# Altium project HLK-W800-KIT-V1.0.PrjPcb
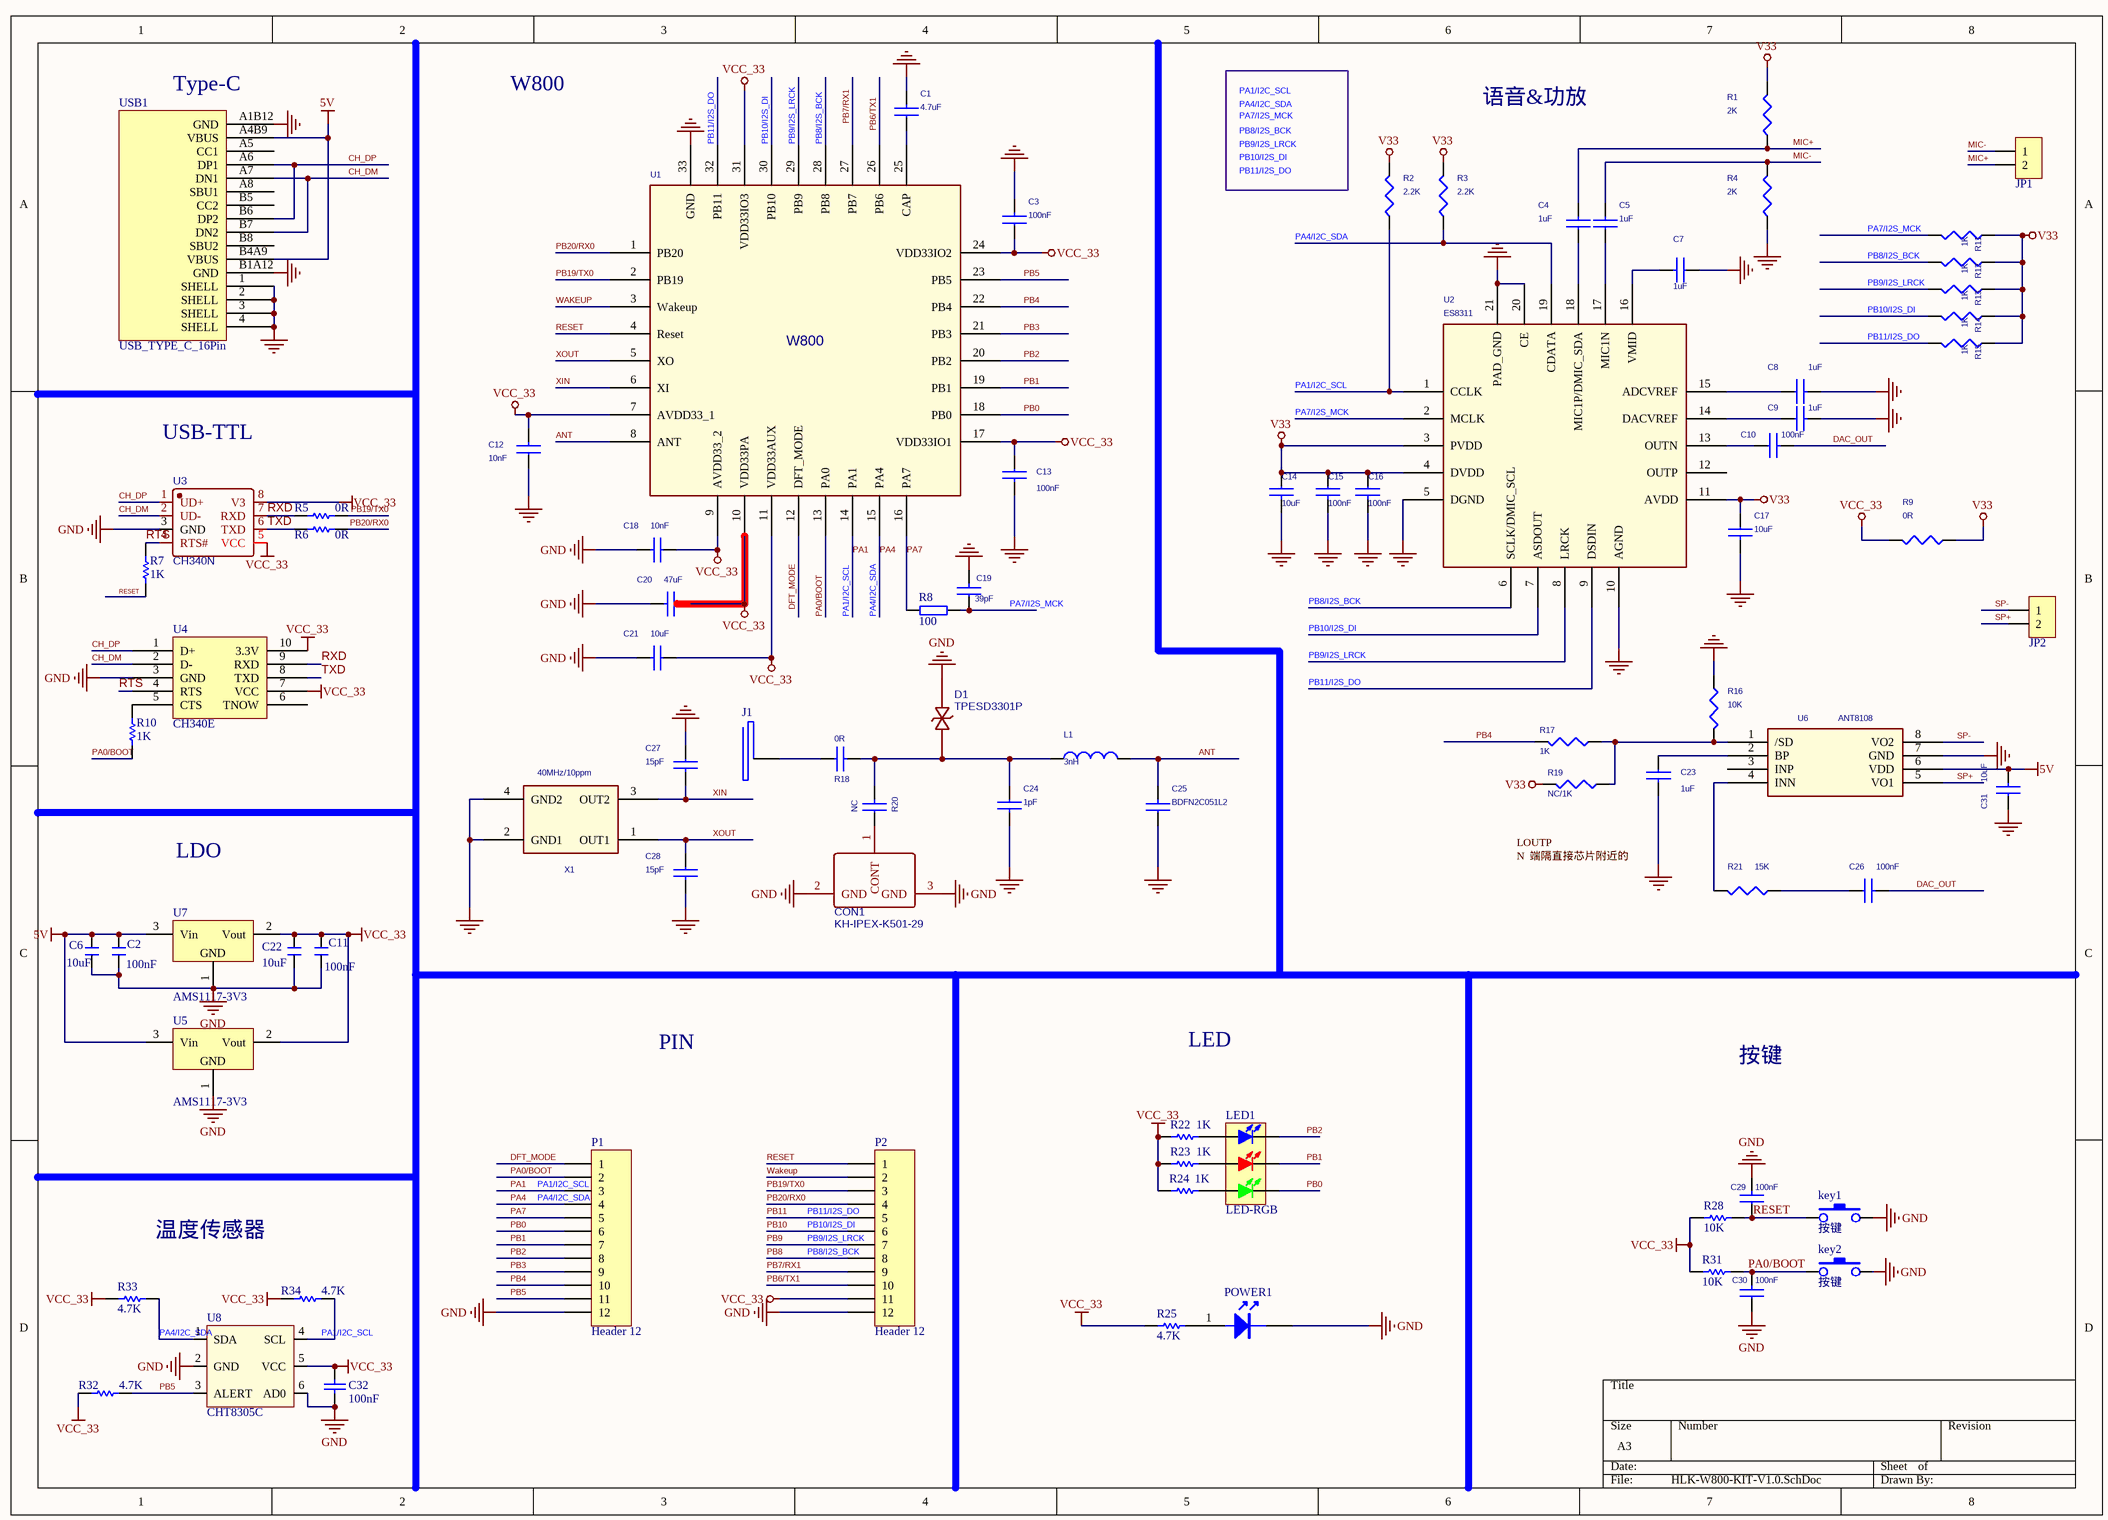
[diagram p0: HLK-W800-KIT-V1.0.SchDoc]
1 sheet, 84 parts. Net scope: global (net labels, ports and power ports of the same name join across sheets).
Board file: HLK-W800-KIT-V1.0.PcbDoc

## Sheet HLK-W800-KIT-V1.0.SchDoc
size A3

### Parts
C1  4.7uF  [C 0402_L]
C2  100nF  [C 0603_L]
C3  100nF  [C 0402_L]
C4  1uF  [C 0402_L]
C5  1uF  [C 0402_L]
C6  10uF  [C 0603_L]
C7  1uF  [C 0402_L]
C8  1uF  [C 0402_L]
C9  1uF  [C 0402_L]
C10  100nF  [C 0402_L]
C11  100nF  [C 0603_L]
C12  10nF  [C 0402_L]
C13  100nF  [C 0402_L]
C14  10uF  [C 0402_L]
C15  100nF  [C 0402_L]
C16  100nF  [C 0402_L]
C17  10uF  [C 0402_L]
C18  10nF  [C 0402_L]
C19  39pF  [C 0402_L]
C20  47uF  [C 0805_L]
C21  10uF  [C 0603_L]
C22  10uF  [C 0603_L]
C23  1uF  [C 0402_L]
C24  1pF  [C 0402_L]
C25  BDFN2C051L2  [C 0402_L]
C26  100nF  [C 0402_L]
C27  15pF  [C 0402_L]
C28  15pF  [C 0402_L]
C29  100nF  [0603]
C30  100nF  [0603]
C31  10uF  [C 0402_L]
C32  100nF  [C 0603_L]
CON1  KH-IPEX-K501-29  [SMA/UFLR/NI]
D1  TPESD3301P  [C 0402_L]
J1  (no value)  [TX1]
JP1  HDR-1X2  [MX 1.25-LS-2P]  (value not drawn)
JP2  HDR-1X2  [PH2.0-LS-2P]  (value not drawn)
key1  按键  [正按小龟]
key2  按键  [正按小龟]
L1  3nH  [0402A]
LED1  LED-RGB  [LED 5050]
P1  Header 12  [HDR1X12]
P2  Header 12  [HDR1X12]
POWER1  (no value)  [LED0603]
R1  2K  [R 0402_L]
R2  2.2K  [R 0402_L]
R3  2.2K  [R 0402_L]
R4  2K  [R 0402_L]
R5  0R  [R 0603_L]
R6  0R  [R 0603_L]
R7  1K  [R 0603_L]
R8  100  [R 0402_L]
R9  0R  [R 0805_L]
R10  1K  [R 0603_L]
R11  1K  [R 0402_L]
R12  1K  [R 0402_L]
R13  1K  [R 0402_L]
R14  1K  [R 0402_L]
R15  1K  [R 0402_L]
R16  10K  [R 0402_L]
R17  1K  [R 0402_L]
R18  0R  [C 0402_L]
R19  NC/1K  [R 0402_L]
R20  NC  [C 0402_L]
R21  15K  [R 0402_L]
R22  1K  [R 0603_L]
R23  1K  [R 0603_L]
R24  1K  [R 0603_L]
R25  4.7K  [R 0603_L]
R28  10K  [0603]
R31  10K  [0603]
R32  4.7K  [R 0603_L]
R33  4.7K  [R 0603_L]
R34  4.7K  [R 0603_L]
U1  W800  [QFN32_4X4]
U2  ES8311  [ES8311]
U3  CH340N  [SOP8_L]
U4  CH340E  [MSOP10_L]
U5  AMS1117-3V3  [SOT89_L]
U6  ANT8108  [SOP8_L]
U7  AMS1117-3V3  [SOT223_L]
U8  CHT8305C  [DFN6 3X3]
USB1  USB_TYPE_C_16Pin  [USB-C-16PIN-1]
X1  40MHz/10ppm  [SMD-3225]

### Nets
5V: C2.2 C6.2 C31.2 U5.3(Vin) U6.6(VDD) U7.3(Vin) USB1.A4B9(VBUS) USB1.B4A9(VBUS)
GND: C1.2 C2.1 C3.2 C6.1 C7.1 C8.2 C9.2 C11.1 C12.1 C13.2 C14.2 C15.2 C16.2 C17.2 C18.2 C19.2 C20.2 C21.2 C22.1 C23.2 C24.2 C25.1 C27.1 C28.2 C29.2 C30.1 C31.1 C32.2 CON1.2(GND) CON1.3(GND) D1.2 key1.2 key2.2 P1.12 P2.12 POWER1.2(K) R4.2 R16.1 U1.33(GND) U2.5(DGND) U2.10(AGND) U2.20(CE) U2.21(PAD_GND) U3.3(GND) U4.3(GND) U5.1(GND) U6.7(GND) U7.1(GND) U8.2(GND) U8.6(AD0) USB1.1(SHELL) USB1.2(SHELL) USB1.3(SHELL) USB1.4(SHELL) USB1.A1B12(GND) USB1.B1A12(GND) X1.2(GND1) X1.4(GND2)
V33: C14.1 C15.1 C16.1 C17.1 R1.1 R2.2 R3.2 R9.1 R11.1 R12.1 R13.1 R14.1 R15.1 R19.2 U2.3(PVDD) U2.4(DVDD) U2.11(AVDD)
VCC_33: C3.1 C11.2 C12.2 C13.1 C18.1 C20.1 C21.1 C22.2 C32.1 P2.11 R9.2 R22.1 R23.1 R24.1 R25.1 R28.2 R31.2 R32.1 R33.2 R34.1 U1.7(AVDD33_1) U1.9(AVDD33_2) U1.10(VDD33PA) U1.11(VDD33AUX) U1.17(VDD33IO1) U1.24(VDD33IO2) U1.31(VDD33IO3) U3.5(VCC) U3.8(V3) U4.7(VCC) U4.10(3.3V) U5.2(Vout) U7.2(Vout) U8.5(VCC)
ANT: C25.2 L1.1 U1.8(ANT)
CH_DM: U3.2(UD-) U4.2(D-) USB1.A7(DN1) USB1.B7(DN2)
CH_DP: U3.1(UD+) U4.1(D+) USB1.A6(DP1) USB1.B6(DP2)
DAC_OUT: C10.2 C26.2
DFT_MODE: P1.1 U1.12(DFT_MODE)
MIC+: C4.2 JP1.2 R1.2
MIC-: C5.2 JP1.1 R4.1
PA0/BOOT: C30.2 key2.1 P1.2 R10.1 R31.1 U1.13(PA0)
PA1: P1.3 R2.1 R34.2 U1.14(PA1) U2.1(CCLK) U8.4(SCL)  [also labelled PA1/I2C_SCL]
PA4: P1.4 R3.1 R33.1 U1.15(PA4) U2.19(CDATA) U8.1(SDA)  [also labelled PA4/I2C_SDA]
PA7: P1.5 R8.1 U1.16(PA7)
PA7/I2S_MCK: C19.1 R8.2 R11.2 U2.2(MCLK)
PB0: LED1.4(GREEN_K) P1.6 U1.18(PB0)
PB1: LED1.5(RED_K) P1.7 U1.19(PB1)
PB2: LED1.6(BULE_K) P1.8 U1.20(PB2)
PB3: P1.9 U1.21(PB3)
PB4: P1.10 R17.2 U1.22(PB4)
PB5: P1.11 R32.2 U1.23(PB5) U8.3(ALERT)
PB6/TX1: P2.10 U1.26(PB6)
PB7/RX1: P2.9 U1.27(PB7)
PB8: P2.8 R12.2 U1.28(PB8) U2.6(SCLK/DMIC_SCL)  [also labelled PB8/I2S_BCK]
PB9: P2.7 R13.2 U1.29(PB9) U2.8(LRCK)  [also labelled PB9/I2S_LRCK]
PB10: P2.6 R14.2 U1.30(PB10) U2.7(ASDOUT)  [also labelled PB10/I2S_DI]
PB11: P2.5 R15.2 U1.32(PB11) U2.9(DSDIN)  [also labelled PB11/I2S_DO]
PB19/TX0: P2.3 R5.2 U1.2(PB19)
PB20/RX0: P2.4 R6.2 U1.1(PB20)
RESET: C29.1 key1.1 P2.1 R7.1 R28.1 U1.4(Reset)
RTS: R7.2 U3.4(RTS#) U4.4(RTS)
RXD: R5.1 U3.7(RXD) U4.9(RXD)
SP+: JP2.2 U6.5(VO1)
SP-: JP2.1 U6.8(VO2)
TXD: R6.1 U3.6(TXD) U4.8(TXD)
Wakeup: P2.2 U1.3(Wakeup)
XIN: C27.2 U1.6(XI) X1.3(OUT2)
XOUT: C28.1 U1.5(XO) X1.1(OUT1)
NetC1_1: C1.1 U1.25(CAP)
NetC4_1: C4.1 U2.18(MIC1P/DMIC_SDA)
NetC5_1: C5.1 U2.17(MIC1N)
NetC7_2: C7.2 U2.16(VMID)
NetC8_1: C8.1 U2.15(ADCVREF)
NetC9_1: C9.1 U2.14(DACVREF)
NetC10_1: C10.1 U2.13(OUTN)
NetC23_1: C23.1 U6.2(BP)
NetC24_1: C24.1 D1.1 L1.2 R18.2 R20.2
NetC26_1: C26.1 R21.1
NetCON1_1: CON1.1(CONT) R20.1
NetJ1_1: J1.1 R18.1
NetLED1_1: LED1.1(BULE_A) R22.2
NetLED1_2: LED1.2(RED_A) R23.2
NetLED1_3: LED1.3(GREEN_A) R24.2
NetPOWER1_1: POWER1.1(A) R25.2
NetR10_2: R10.2 U4.5(CTS)
NetR16_2: R16.2 R17.1 R19.1 U6.1(/SD)
NetR21_2: R21.2 U6.4(INN)

Not connected (* = marked no-connect by the designer): U2 12(OUTP); U4 6(TNOW); U6 3(INP); USB1 A5(CC1) A8(SBU1) B5(CC2) B8(SBU2)

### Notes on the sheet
- (near USB1) Type-C
- W800
- 语音&功放
- USB-TTL
- LDO
- LOUTP
- N
- 端隔直接芯片附近的
- PIN
- LED
- 按键
- 温度传感器
- Labels drawn without touching a wire or pin: PA1/I2C_SCL, PA4/I2C_SDA, PA7/I2S_MCK, PB8/I2S_BCK, PB9/I2S_LRCK, PB10/I2S_DI, PB11/I2S_DO

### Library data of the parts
C1 C3-C5 C7-C10 C12-C21 C23 C24 C26 C31 R18 R20 = CAP NP_Dup2
C2 C6 C11 C22 = C: 无极性贴片电容; 版权归属: 源创客
C25 = CAP NP
C27-C30 = CAP NP_Dup1
C32 = Cap: Capacitor; Value: 100pF
CON1 = KH-IPEX-K501-29: BOM_Manufacturer: Shenzhen Kinghelm Elec; Contributor: LCSC
D1 = PT05D5CE: BOM_Manufacturer: PTTC(Polytronics Tech); Contributor: LCSC
J1 = Component_1
JP1 JP2 = Header 2: 2P接插件; 版权归属: 源创客
L1 = INDUCTOR
LED1 = LED-RGB: 三基色LED; 版权归属: 源创客
P1 P2 = Header 12: Header, 12-Pin
POWER1 = LED
R1 = R_Dup1: ROOM: FPGA_BANK3_4_CLK; REUSE_ANNOTATE: TRUE
R2 R3 R9 R16 R21 = RES
R4 = R_Dup1: REUSE_ANNOTATE: TRUE; ROOM: FPGA_BANK3_4_CLK
R5-R7 R10 R22-R25 R28 R31-R34 = Res1: Resistor
R8 = RES1: R?
R11-R15 R17 R19 = R
U1 = W600_10
U2 = ES8374_0
U3 = CH340N: BOM_Manufacturer: WCH(Jiangsu Qin Heng); Contributor: LCSC
U5 U7 = AMS1117: 三端稳压芯片; BOM名称: 稳压芯片; 版权归属: 源创客
U6 = W25Q16_5: REUSE_ANNOTATE: TRUE
U8 = CHT8305C: 温度传感器
X1 = OSC44M_5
